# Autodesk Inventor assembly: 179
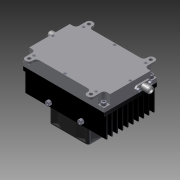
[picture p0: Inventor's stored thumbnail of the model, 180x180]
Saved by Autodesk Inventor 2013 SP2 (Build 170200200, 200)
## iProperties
Created: 2017-09
Part Number: 179
Document SubType Name: Assembly
Designer: CFD
Author: CFD
Translation Standard: STEP AP214IS
FileName: \\SERPENTOR\Engineering\ENG\Models\TTRMxxxx\TTRM1190\Inventor\TTRM1190-HSF.stp
PreProcessor: Autodesk Inventor 2013
PostProcessor: Build: 200, Release: 2013 SP2 - Date: Fri 04/19/2013
Sent Units: inch
Uncertainty: 0.00039370078740199997
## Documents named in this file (11)
- \\SERPENTOR\Engineering\ENG\Models\TTRMxxxx\TTRM1190\Inventor\Imported Components\TTRM1190-HSF\179.iam
- \\SERPENTOR\Engineering\ENG\Models\TTRMxxxx\TTRM1190\Inventor\Imported Components\TTRM1190-HSF\T531491015.ipt
- \\SERPENTOR\Engineering\ENG\Models\TTRMxxxx\TTRM1190\Inventor\Imported Components\TTRM1190-HSF\410-003.ipt
- \\SERPENTOR\Engineering\ENG\Models\TTRMxxxx\TTRM1190\Inventor\Imported Components\TTRM1190-HSF\Cross Recessed Flat Countersunk Head Machine Screw - Type I - Inch 0-80 x 1_8.ipt
- \\SERPENTOR\Engineering\ENG\Models\TTRMxxxx\TTRM1190\Inventor\Imported Components\TTRM1190-HSF\Hexagon Socket Head Cap Screw - Inch No. 2 - 56 UNC - 3_16.ipt
- \\SERPENTOR\Engineering\ENG\Models\TTRMxxxx\TTRM1190\Inventor\Imported Components\TTRM1190-HSF\T501491010.ipt
- \\SERPENTOR\Engineering\ENG\Models\TTRMxxxx\TTRM1190\Inventor\Imported Components\TTRM1190-HSF\T521491010.ipt
- \\SERPENTOR\Engineering\ENG\Models\TTRMxxxx\TTRM1190\Inventor\Imported Components\TTRM1190-HSF\Hexagon Socket Head Cap Screw - Inch No. 4 - 40 UNC - 1_4.ipt
- \\SERPENTOR\Engineering\ENG\Models\TTRMxxxx\TTRM1190\Inventor\Imported Components\TTRM1190-HSF\260-007.iam
- \\SERPENTOR\Engineering\ENG\Models\TTRMxxxx\TTRM1190\Inventor\Imported Components\TTRM1190-HSF\600-010.ipt
- \\SERPENTOR\Engineering\ENG\Models\TTRMxxxx\TTRM1190\Inventor\Imported Components\TTRM1190-HSF\Hexagon Socket Head Cap Screw - Inch No. 4 - 40 UNC - 1_4_1.ipt
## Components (26 placed, 10 different names)
1. T531491015:1
2. 410-003:1
3. 410-003:2
4. Cross Recessed Flat Countersunk Head Machine Screw - Type I - Inch 0-80 x 1_8:1
5. Cross Recessed Flat Countersunk Head Machine Screw - Type I - Inch 0-80 x 1_8:2
6. Cross Recessed Flat Countersunk Head Machine Screw - Type I - Inch 0-80 x 1_8:3
7. Cross Recessed Flat Countersunk Head Machine Screw - Type I - Inch 0-80 x 1_8:4
8. Cross Recessed Flat Countersunk Head Machine Screw - Type I - Inch 0-80 x 1_8:5
9. Cross Recessed Flat Countersunk Head Machine Screw - Type I - Inch 0-80 x 1_8:6
10. Cross Recessed Flat Countersunk Head Machine Screw - Type I - Inch 0-80 x 1_8:7
11. Cross Recessed Flat Countersunk Head Machine Screw - Type I - Inch 0-80 x 1_8:8
12. Hexagon Socket Head Cap Screw - Inch No. 2 - 56 UNC - 3_16:1
13. Hexagon Socket Head Cap Screw - Inch No. 2 - 56 UNC - 3_16:2
14. Hexagon Socket Head Cap Screw - Inch No. 2 - 56 UNC - 3_16:3
15. Hexagon Socket Head Cap Screw - Inch No. 2 - 56 UNC - 3_16:4
16. T501491010:1
17. T521491010:1
18. Hexagon Socket Head Cap Screw - Inch No. 4 - 40 UNC - 1_4:1
19. Hexagon Socket Head Cap Screw - Inch No. 4 - 40 UNC - 1_4:2
20. Hexagon Socket Head Cap Screw - Inch No. 4 - 40 UNC - 1_4:3
21. Hexagon Socket Head Cap Screw - Inch No. 4 - 40 UNC - 1_4:4
22. 260-007:1 [sub-assembly]
23. 600-010:1
24. 600-010:2
25. Hexagon Socket Head Cap Screw - Inch No. 4 - 40 UNC - 1_4_1:1
26. Hexagon Socket Head Cap Screw - Inch No. 4 - 40 UNC - 1_4_1:2
